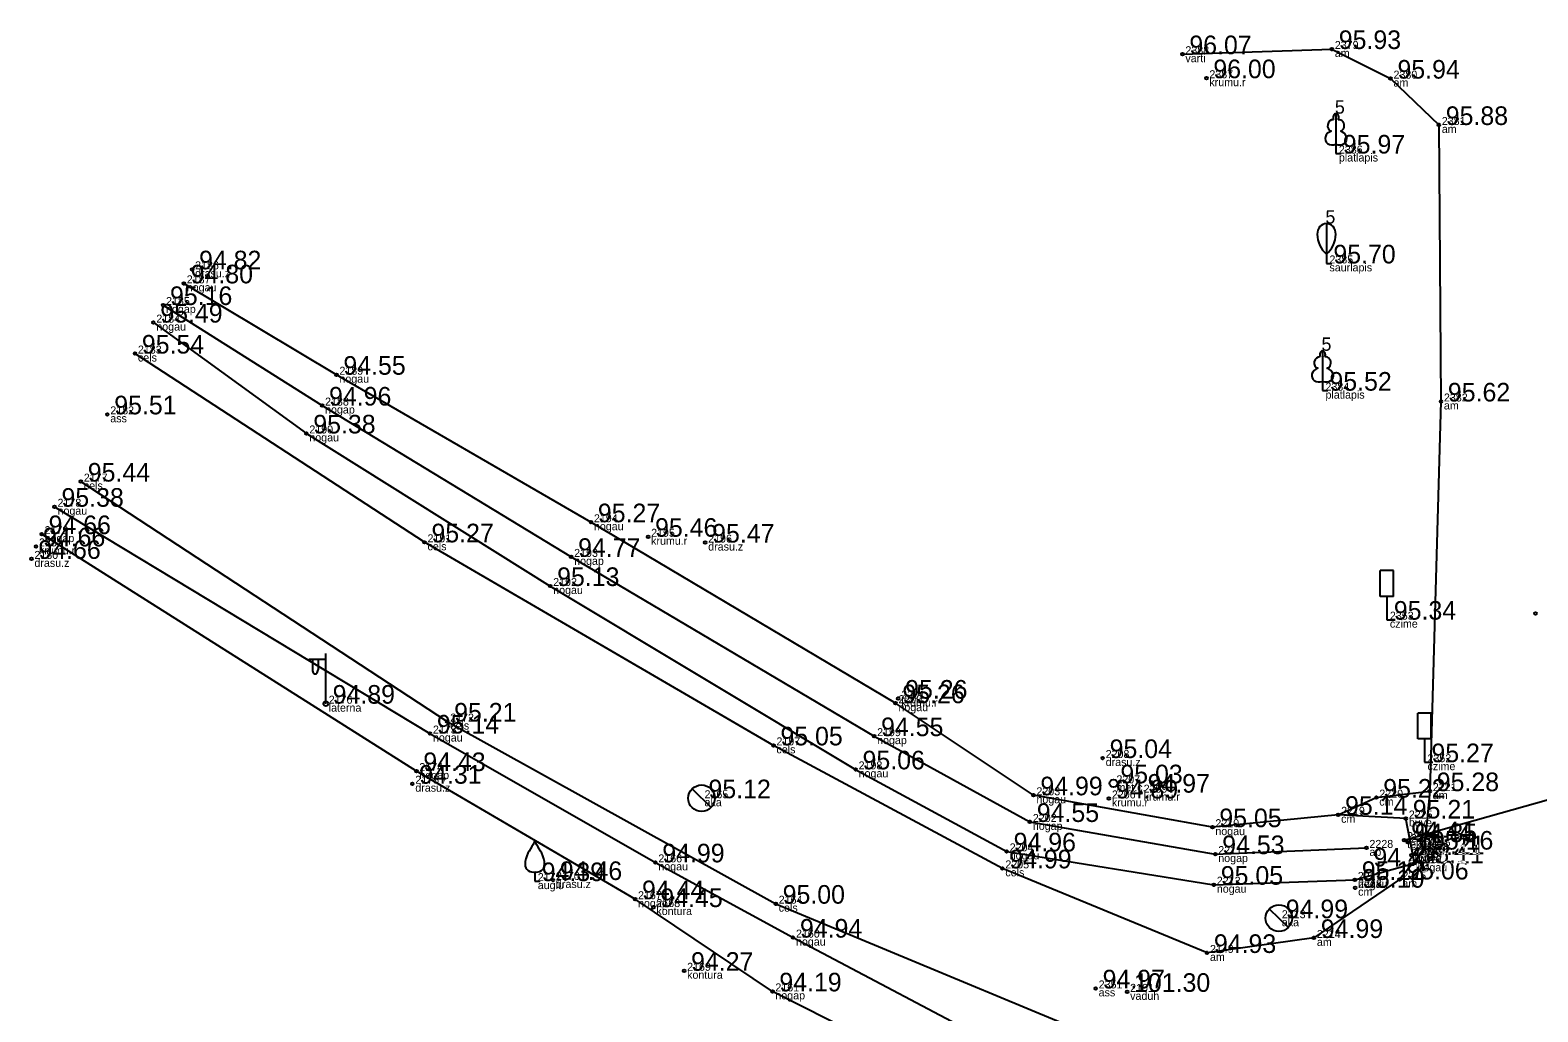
# Model space of a CAD drawing. Extents: x 614911 to 615803, y 262110 to 264311.
# Drawn here: x 615573.6 to 615630.3, y 263602.8 to 263639.7 of the extents above; entities that cross this region are included whole.
import ezdxf

# ---------------------------------------------------------------- set-up
doc = ezdxf.new("R2010")
doc.units = 0
for name, color, linetype in [('Level 1', 7, 'Continuous'), ('Level 11', 7, 'Continuous'), ('Level 12', 7, 'Continuous'), ('Level 14', 7, 'Continuous'), ('Level 16', 7, 'Continuous'), ('Level 31', 7, 'Continuous'), ('Level 37', 7, 'Continuous'), ('Level 44', 7, 'Continuous'), ('Level 53', 7, 'Continuous'), ('Level 54', 7, 'Continuous'), ('Level 57', 7, 'Continuous'), ('Level 58', 7, 'Continuous')]:
    doc.layers.add(name, color=color, linetype=linetype)

msp = doc.modelspace()

# ---------------------------------------------------------------- linework, layer by layer
at = {"layer": 'Level 1'}
for p, q in [((615622.678, 263635.413), (615622.678, 263635.066)), ((615622.678, 263635.066), (615622.878, 263635.066)), ((615622.322, 263631.284), (615622.322, 263630.932)), ((615622.322, 263630.932), (615622.522, 263630.932)), ((615622.174, 263626.492), (615622.174, 263626.145)), ((615622.174, 263626.145), (615622.374, 263626.145)), ((615592.559, 263608.045), (615592.559, 263607.693)), ((615592.559, 263607.693), (615592.759, 263607.693))]:
    msp.add_line(p, q, dxfattribs=at)
for points in [[(615622.678, 263636.566), (615622.678, 263635.413)], [(615622.768, 263636.334), (615622.767, 263636.335)], [(615622.322, 263632.432), (615622.322, 263631.284)], [(615622.174, 263627.645), (615622.174, 263626.492)], [(615622.264, 263627.413), (615622.263, 263627.414)]]:
    msp.add_lwpolyline(points, dxfattribs=at)
for centre, radius, start, end in [((615605.184, 263601.297), 14.88, 148.4844, 149.9901), ((615592.142, 263609.331), 0.439, 324.3837, 341.712), ((615592.976, 263609.331), 0.439, 198.288, 215.6163), ((615579.934, 263601.297), 14.88, 30.0099, 31.5156), ((615593.083, 263608.318), 0.89, 151.757, 179.9138), ((615592.483, 263608.324), 0.29, 181.0782, 285.2823), ((615592.635, 263608.324), 0.29, 254.7177, 358.9218), ((615592.035, 263608.318), 0.89, 0.0862, 28.243)]:
    msp.add_arc(centre, radius, start, end, dxfattribs=at)
for centre, major_axis, ratio, start_param, end_param in [((615622.55, 263636.121), (-0.039, -0.212), 0.861323, 3.141593, 6.283185), ((615622.678, 263636.416), (0, -0.15), 0.707107, 3.14537, 5.287485), ((615622.678, 263636.416), (0, -0.15), 0.707107, 0.995701, 3.137816), ((615622.806, 263636.121), (0.039, -0.212), 0.861323, 0, 3.141593), ((615622.588, 263635.659), (0.307, 0.095), 0.814445, 1.570796, 4.752015), ((615622.768, 263635.659), (-0.307, 0.095), 0.814445, 1.531171, 4.712389), ((615622.322, 263632.032), (0, 0.4), 0.875, 0, 1.570796), ((615622.322, 263632.032), (0, -0.4), 0.875, 1.570796, 3.141593), ((615622.797, 263632.055), (0, -0.943), 0.875, 4.7372, 5.669711), ((615621.847, 263632.055), (0, -0.943), 0.875, 0.613474, 1.545985), ((615622.174, 263627.495), (0, -0.15), 0.707107, 3.14537, 5.287485), ((615622.174, 263627.495), (0, -0.15), 0.707107, 0.995701, 3.137816), ((615622.046, 263627.2), (-0.039, -0.212), 0.861323, 3.141593, 6.283185), ((615622.302, 263627.2), (0.039, -0.212), 0.861323, 0, 3.141593), ((615622.084, 263626.738), (0.307, 0.095), 0.814445, 1.570796, 4.752015), ((615622.264, 263626.738), (-0.307, 0.095), 0.814445, 1.531171, 4.712389)]:
    msp.add_ellipse(centre, major_axis=major_axis, ratio=ratio, start_param=start_param, end_param=end_param, dxfattribs=at)
at = {"layer": 'Level 11'}
msp.add_line((615625.244, 263609.235), (615637.058, 263612.559), dxfattribs=at)
at = {"layer": 'Level 12'}
for p, q in [((615598.47, 263611.159), (615599.188, 263610.463)), ((615620.173, 263606.645), (615620.891, 263605.949))]:
    msp.add_line(p, q, dxfattribs=at)
for centre in [(615598.829, 263610.811), (615620.532, 263606.297)]:
    msp.add_circle(centre, 0.5, dxfattribs=at)
at = {"layer": 'Level 14'}
msp.add_circle((615614.315, 263611.373), 0.148, dxfattribs=at)
at = {"layer": 'Level 16'}
for p, q in [((615624.841, 263619.376), (615624.341, 263619.376)), ((615624.341, 263618.407), (615624.341, 263619.376)), ((615624.841, 263618.407), (615624.841, 263619.376)), ((615624.841, 263618.407), (615624.341, 263618.407)), ((615624.595, 263618.407), (615624.595, 263617.529)), ((615624.595, 263617.529), (615624.91, 263617.529)), ((615626.255, 263614.014), (615625.755, 263614.014)), ((615625.755, 263613.045), (615625.755, 263614.014)), ((615626.255, 263613.045), (615626.255, 263614.014)), ((615626.255, 263613.045), (615625.755, 263613.045)), ((615626.009, 263613.045), (615626.009, 263612.167)), ((615626.009, 263612.167), (615626.324, 263612.167))]:
    msp.add_line(p, q, dxfattribs=at)
at = {"layer": 'Level 31'}
for points in [[(615623.39, 263607.738), (615625.634, 263608.363), (615625.308, 263610.049), (615622.762, 263610.188), (615618.034, 263609.723), (615611.307, 263610.922), (615606.119, 263614.387), (615594.67, 263621.194), (615585.102, 263626.744), (615579.362, 263630.182)], [(615578.584, 263629.367), (615584.563, 263625.584), (615593.927, 263619.891), (615605.317, 263613.147), (615611.172, 263609.919), (615618.143, 263608.71), (615623.826, 263608.943)], [(615578.218, 263628.706), (615583.971, 263624.535), (615593.139, 263618.796), (615604.621, 263611.898), (615610.301, 263608.812), (615618.089, 263607.558), (615623.39, 263607.738)], [(615574.504, 263621.778), (615588.618, 263613.245), (615597.092, 263608.399), (615602.267, 263605.568), (615610.435, 263601.26), (615615.838, 263599.469), (615621.811, 263597.513), (615625.283, 263594.837), (615626.379, 263591.004)], [(615626.379, 263591.004), (615624.359, 263592.45), (615617.225, 263594.934), (615614.681, 263596.186), (615610.011, 263599.223), (615601.492, 263603.545), (615596.329, 263607.013), (615588.108, 263611.833), (615574.019, 263620.747)]]:
    msp.add_lwpolyline(points, dxfattribs=at)
at = {"layer": 'Level 37'}
for points in [[(615616.907, 263638.803), (615622.525, 263638.998), (615624.732, 263637.885), (615626.547, 263636.14), (615626.627, 263625.738), (615626.209, 263611.078), (615625.993, 263608.879), (615625.064, 263607.755), (615621.851, 263605.554), (615617.831, 263604.991), (615610.138, 263608.173), (615601.533, 263612.8), (615588.414, 263620.439), (615577.526, 263627.541)], [(615575.493, 263622.724), (615589.267, 263613.696), (615601.617, 263606.844), (615617.294, 263600.321), (615621.316, 263599.948), (615622.689, 263599.881), (615623.501, 263599.431), (615622.954, 263597.67), (615621.811, 263597.513), (615621.119, 263598.545), (615621.386, 263599.38), (615622.689, 263599.881)], [(615622.762, 263610.188), (615624.197, 263610.834), (615626.209, 263611.078)]]:
    msp.add_lwpolyline(points, dxfattribs=at)
at = {"layer": 'Level 44'}
for p, q in [((615584.699, 263614.369), (615584.699, 263616.252)), ((615584.699, 263616.032), (615584.064, 263616.032)), ((615584.199, 263616.032), (615584.199, 263615.64)), ((615584.409, 263616.032), (615584.409, 263615.64))]:
    msp.add_line(p, q, dxfattribs=at)
msp.add_circle((615584.699, 263614.369), 0.09, dxfattribs=at)
msp.add_ellipse((615584.304, 263615.64), major_axis=(0, 0.151), ratio=0.695971, start_param=1.570796, end_param=4.712389, dxfattribs=at)
at = {"layer": 'Level 57'}
for centre in [(615622.525, 263638.998), (615616.907, 263638.803), (615617.809, 263637.9), (615624.732, 263637.885), (615626.547, 263636.14), (615579.676, 263630.709), (615579.362, 263630.182), (615578.584, 263629.367), (615578.218, 263628.706), (615577.526, 263627.541), (615585.102, 263626.744), (615576.488, 263625.254), (615584.563, 263625.584), (615626.627, 263625.738), (615583.971, 263624.535), (615575.493, 263622.724), (615574.504, 263621.778), (615574.019, 263620.747), (615594.67, 263621.194), (615573.808, 263620.286), (615588.414, 263620.439), (615596.82, 263620.648), (615598.967, 263620.43), (615573.636, 263619.816), (615593.927, 263619.891), (615593.139, 263618.796), (615630.18, 263617.767), (615606.223, 263614.558), (615606.119, 263614.387), (615589.267, 263613.696), (615588.618, 263613.245), (615601.533, 263612.8), (615605.317, 263613.147), (615613.91, 263612.324), (615588.108, 263611.833), (615604.621, 263611.898), (615587.955, 263611.357), (615626.209, 263611.078), (615611.307, 263610.922), (615614.143, 263610.804), (615615.338, 263611.021), (615624.197, 263610.834), (615622.762, 263610.188), (615625.308, 263610.049), (615611.172, 263609.919), (615618.034, 263609.723), (615610.301, 263608.812), (615623.826, 263608.943), (615625.244, 263609.235), (615625.384, 263609.16), (615625.993, 263608.879), (615597.092, 263608.399), (615618.143, 263608.71), (615625.519, 263608.672), (615625.634, 263608.363), (615625.667, 263608.704), (615593.242, 263607.735), (615610.138, 263608.173), (615623.39, 263607.738), (615625.064, 263607.755), (615618.089, 263607.558), (615623.401, 263607.446), (615596.329, 263607.013), (615597.019, 263606.717), (615601.617, 263606.844), (615602.267, 263605.568), (615621.851, 263605.554), (615617.831, 263604.991), (615598.174, 263604.32), (615601.492, 263603.545), (615613.646, 263603.657), (615614.829, 263603.527)]:
    msp.add_circle(centre, 0.05, dxfattribs=at)
at = {"layer": 'Level 58'}
for centre in [(615622.525, 263638.998), (615616.907, 263638.803), (615617.809, 263637.9), (615624.732, 263637.885), (615626.547, 263636.14), (615579.676, 263630.709), (615579.362, 263630.182), (615578.584, 263629.367), (615578.218, 263628.706), (615577.526, 263627.541), (615585.102, 263626.744), (615576.488, 263625.254), (615584.563, 263625.584), (615626.627, 263625.738), (615583.971, 263624.535), (615575.493, 263622.724), (615574.504, 263621.778), (615574.019, 263620.747), (615594.67, 263621.194), (615573.808, 263620.286), (615588.414, 263620.439), (615596.82, 263620.648), (615598.967, 263620.43), (615573.636, 263619.816), (615593.927, 263619.891), (615593.139, 263618.796), (615630.18, 263617.767), (615606.223, 263614.558), (615606.119, 263614.387), (615589.267, 263613.696), (615588.618, 263613.245), (615601.533, 263612.8), (615605.317, 263613.147), (615613.91, 263612.324), (615588.108, 263611.833), (615604.621, 263611.898), (615587.955, 263611.357), (615626.209, 263611.078), (615611.307, 263610.922), (615614.143, 263610.804), (615615.338, 263611.021), (615624.197, 263610.834), (615622.762, 263610.188), (615625.308, 263610.049), (615611.172, 263609.919), (615618.034, 263609.723), (615610.301, 263608.812), (615623.826, 263608.943), (615625.244, 263609.235), (615625.384, 263609.16), (615625.993, 263608.879), (615597.092, 263608.399), (615618.143, 263608.71), (615625.519, 263608.672), (615625.634, 263608.363), (615625.667, 263608.704), (615593.242, 263607.735), (615610.138, 263608.173), (615623.39, 263607.738), (615625.064, 263607.755), (615618.089, 263607.558), (615623.401, 263607.446), (615596.329, 263607.013), (615597.019, 263606.717), (615601.617, 263606.844), (615602.267, 263605.568), (615621.851, 263605.554), (615617.831, 263604.991), (615598.174, 263604.32), (615601.492, 263603.545), (615613.646, 263603.657), (615614.829, 263603.527)]:
    msp.add_circle(centre, 0.05, dxfattribs=at)

# ---------------------------------------------------------------- texts
at = {"layer": 'Level 1'}
for p in [(615622.453, 263636.566), (615622.097, 263632.432), (615621.949, 263627.645)]:
    msp.add_text(' 5', height=0.5, dxfattribs=at).set_placement(p)
at = {"layer": 'Level 53'}
for s, p in [(' am', (615622.525, 263638.698)), (' varti', (615616.907, 263638.503)), (' krumu.r', (615617.809, 263637.6)), (' am', (615624.732, 263637.585)), (' am', (615626.547, 263635.84)), (' platlapis', (615622.678, 263634.766)), (' drasu.z', (615579.676, 263630.409)), (' saurlapis', (615622.322, 263630.632)), (' nogau', (615579.362, 263629.882)), (' nogap', (615578.584, 263629.067)), (' nogau', (615578.218, 263628.406)), (' cels', (615577.526, 263627.241)), (' nogau', (615585.102, 263626.444)), (' platlapis', (615622.174, 263625.845)), (' nogap', (615584.563, 263625.284)), (' am', (615626.627, 263625.438)), (' ass', (615576.488, 263624.954)), (' nogau', (615583.971, 263624.235)), (' cels', (615575.493, 263622.424)), (' nogau', (615574.504, 263621.478)), (' nogau', (615594.67, 263620.894)), (' krumu.r', (615573.808, 263619.986)), (' nogap', (615574.019, 263620.447)), (' cels', (615588.414, 263620.139)), (' krumu.r', (615596.82, 263620.348)), (' drasu.z', (615598.967, 263620.13)), (' drasu.z', (615573.636, 263619.516)), (' nogap', (615593.927, 263619.591)), (' nogau', (615593.139, 263618.496)), (' czime', (615624.595, 263617.229)), (' krumu.r', (615606.223, 263614.258)), (' laterna', (615584.699, 263614.069)), (' nogau', (615606.119, 263614.087)), (' cels', (615589.267, 263613.396)), (' nogau', (615588.618, 263612.945)), (' nogap', (615605.317, 263612.847)), (' cels', (615601.533, 263612.5)), (' drasu.z', (615613.91, 263612.024)), (' nogap', (615588.108, 263611.533)), (' nogau', (615604.621, 263611.598)), (' czime', (615626.009, 263611.867)), (' drasu.z', (615587.955, 263611.057)), (' met.c.', (615614.315, 263611.073)), (' aka', (615598.829, 263610.511)), (' nogau', (615611.307, 263610.622)), (' krumu.r', (615614.143, 263610.504)), (' krumu.r', (615615.338, 263610.721)), (' cm', (615624.197, 263610.534)), (' am', (615626.209, 263610.778)), (' cm', (615622.762, 263609.888)), (' buve', (615625.308, 263609.749)), (' nogap', (615611.172, 263609.619)), (' nogau', (615618.034, 263609.423)), (' ap', (615623.826, 263608.643)), (' tekne', (615625.244, 263608.935)), (' c.augsa', (615625.384, 263608.86)), (' nogau', (615597.092, 263608.099)), (' nogau', (615610.301, 263608.512)), (' nogap', (615618.143, 263608.41)), (' buve', (615625.519, 263608.372)), (' nogau', (615625.634, 263608.063)), (' buve', (615625.667, 263608.404)), (' am', (615625.993, 263608.579)), (' drasu.z', (615593.242, 263607.435)), (' cels', (615610.138, 263607.873)), (' auglu', (615592.559, 263607.393)), (' nogau', (615618.089, 263607.258)), (' nogau', (615623.39, 263607.438)), (' cm', (615623.401, 263607.146)), (' am', (615625.064, 263607.455)), (' nogap', (615596.329, 263606.713)), (' kontura', (615597.019, 263606.417)), (' cels', (615601.617, 263606.544)), (' aka', (615620.532, 263605.997)), (' nogau', (615602.267, 263605.268)), (' am', (615621.851, 263605.254)), (' am', (615617.831, 263604.691)), (' kontura', (615598.174, 263604.02)), (' nogap', (615601.492, 263603.245)), (' ass', (615613.646, 263603.357)), (' vaduh', (615614.829, 263603.227))]:
    msp.add_text(s, height=0.3, dxfattribs=at).set_placement(p)
at = {"layer": 'Level 54'}
for s, p in [(' 2388', (615616.907, 263638.803)), (' 2379', (615622.525, 263638.998)), (' 2387', (615617.809, 263637.9)), (' 2380', (615624.732, 263637.885)), (' 2381', (615626.547, 263636.14)), (' 2386', (615622.678, 263635.066)), (' 2186', (615579.676, 263630.709)), (' 2385', (615622.322, 263630.932)), (' 2187', (615579.362, 263630.182)), (' 2185', (615578.584, 263629.367)), (' 2184', (615578.218, 263628.706)), (' 2183', (615577.526, 263627.541)), (' 2189', (615585.102, 263626.744)), (' 2384', (615622.174, 263626.145)), (' 2188', (615584.563, 263625.584)), (' 2382', (615626.627, 263625.738)), (' 2182', (615576.488, 263625.254)), (' 2190', (615583.971, 263624.535)), (' 2177', (615575.493, 263622.724)), (' 2178', (615574.504, 263621.778)), (' 2194', (615594.67, 263621.194)), (' 2179', (615574.019, 263620.747)), (' 2195', (615596.82, 263620.648)), (' 2181', (615573.808, 263620.286)), (' 2191', (615588.414, 263620.439)), (' 2193', (615593.927, 263619.891)), (' 2196', (615598.967, 263620.43)), (' 2180', (615573.636, 263619.816)), (' 2192', (615593.139, 263618.796)), (' 2353', (615624.595, 263617.529)), (' 2176', (615584.699, 263614.369)), (' 2200', (615606.119, 263614.387)), (' 2201', (615606.223, 263614.558)), (' 2172', (615589.267, 263613.696)), (' 2173', (615588.618, 263613.245)), (' 2199', (615605.317, 263613.147)), (' 2197', (615601.533, 263612.8)), (' 2208', (615613.91, 263612.324)), (' 2352', (615626.009, 263612.167)), (' 2174', (615588.108, 263611.833)), (' 2198', (615604.621, 263611.898)), (' 2175', (615587.955, 263611.357)), (' 2203', (615611.307, 263610.922)), (' 2207', (615614.315, 263611.373)), (' 2209', (615615.338, 263611.021)), (' 2220', (615624.197, 263610.834)), (' 2221', (615626.209, 263611.078)), (' 2165', (615598.829, 263610.811)), (' 2206', (615614.143, 263610.804)), (' 2202', (615611.172, 263609.919)), (' 2210', (615618.034, 263609.723)), (' 2219', (615622.762, 263610.188)), (' 2225', (615625.308, 263610.049)), (' 2226', (615625.244, 263609.235)), (' 2227', (615625.384, 263609.16)), (' 2204', (615610.301, 263608.812)), (' 2211', (615618.143, 263608.71)), (' 2228', (615623.826, 263608.943)), (' 2224', (615625.519, 263608.672)), (' 2223', (615625.667, 263608.704)), (' 2222', (615625.993, 263608.879)), (' 2166', (615597.092, 263608.399)), (' 2205', (615610.138, 263608.173)), (' 2216', (615625.634, 263608.363)), (' 2171', (615592.559, 263607.693)), (' 2170', (615593.242, 263607.735)), (' 2212', (615618.089, 263607.558)), (' 2217', (615623.39, 263607.738)), (' 2218', (615623.401, 263607.446)), (' 2215', (615625.064, 263607.755)), (' 2167', (615596.329, 263607.013)), (' 2168', (615597.019, 263606.717)), (' 2164', (615601.617, 263606.844)), (' 2213', (615620.532, 263606.297)), (' 2160', (615602.267, 263605.568)), (' 2214', (615621.851, 263605.554)), (' 2149', (615617.831, 263604.991)), (' 2169', (615598.174, 263604.32)), (' 2161', (615601.492, 263603.545)), (' 2351', (615613.646, 263603.657)), (' 2101', (615614.829, 263603.527))]:
    msp.add_text(s, height=0.3, dxfattribs=at).set_placement(p)
at = {"layer": 'Level 58'}
for s, p in [(' 96.07', (615616.907, 263638.803)), (' 95.93', (615622.525, 263638.998)), (' 96.00', (615617.809, 263637.9)), (' 95.94', (615624.732, 263637.885)), (' 95.88', (615626.547, 263636.14)), (' 95.97', (615622.678, 263635.066)), (' 95.70', (615622.322, 263630.932)), (' 94.82', (615579.676, 263630.709)), (' 94.80', (615579.362, 263630.182)), (' 95.16', (615578.584, 263629.367)), (' 95.49', (615578.218, 263628.706)), (' 95.54', (615577.526, 263627.541)), (' 94.55', (615585.102, 263626.744)), (' 95.52', (615622.174, 263626.145)), (' 95.62', (615626.627, 263625.738)), (' 95.51', (615576.488, 263625.254)), (' 94.96', (615584.563, 263625.584)), (' 95.38', (615583.971, 263624.535)), (' 95.44', (615575.493, 263622.724)), (' 95.38', (615574.504, 263621.778)), (' 95.27', (615594.67, 263621.194)), (' 94.66', (615574.019, 263620.747)), (' 95.46', (615596.82, 263620.648)), (' 94.66', (615573.808, 263620.286)), (' 95.27', (615588.414, 263620.439)), (' 95.47', (615598.967, 263620.43)), (' 94.66', (615573.636, 263619.816)), (' 94.77', (615593.927, 263619.891)), (' 95.13', (615593.139, 263618.796)), (' 95.34', (615624.595, 263617.529)), (' 95.26', (615606.119, 263614.387)), (' 95.26', (615606.223, 263614.558)), (' 94.89', (615584.699, 263614.369)), (' 95.21', (615589.267, 263613.696)), (' 95.14', (615588.618, 263613.245)), (' 95.05', (615601.533, 263612.8)), (' 94.55', (615605.317, 263613.147)), (' 95.04', (615613.91, 263612.324)), (' 95.27', (615626.009, 263612.167)), (' 94.43', (615588.108, 263611.833)), (' 95.06', (615604.621, 263611.898)), (' 94.31', (615587.955, 263611.357)), (' 95.03', (615614.315, 263611.373)), (' 94.97', (615615.338, 263611.021)), (' 95.28', (615626.209, 263611.078)), (' 95.12', (615598.829, 263610.811)), (' 94.99', (615611.307, 263610.922)), (' 94.89', (615614.143, 263610.804)), (' 95.22', (615624.197, 263610.834)), (' 94.55', (615611.172, 263609.919)), (' 95.14', (615622.762, 263610.188)), (' 95.21', (615625.308, 263610.049)), (' 95.05', (615618.034, 263609.723)), (' 94.96', (615610.301, 263608.812)), (' 94.44', (615625.244, 263609.235)), (' 94.85', (615625.384, 263609.16)), (' 95.16', (615625.993, 263608.879)), (' 94.99', (615597.092, 263608.399)), (' 94.99', (615610.138, 263608.173)), (' 94.53', (615618.143, 263608.71)), (' 94.47', (615623.826, 263608.243)), (' 95.21', (615625.519, 263608.672)), (' 95.11', (615625.634, 263608.363)), (' 95.21', (615625.667, 263608.704)), (' 94.39', (615592.559, 263607.693)), (' 94.46', (615593.242, 263607.735)), (' 95.12', (615623.39, 263607.738)), (' 95.06', (615625.064, 263607.755)), (' 94.44', (615596.329, 263607.013)), (' 95.05', (615618.089, 263607.558)), (' 95.10', (615623.401, 263607.446)), (' 94.45', (615597.019, 263606.717)), (' 95.00', (615601.617, 263606.844)), (' 94.99', (615620.532, 263606.297)), (' 94.94', (615602.267, 263605.568)), (' 94.99', (615621.851, 263605.554)), (' 94.93', (615617.831, 263604.991)), (' 94.27', (615598.174, 263604.32)), (' 94.97', (615613.646, 263603.657)), (' 94.19', (615601.492, 263603.545)), (' 101.30', (615614.829, 263603.527))]:
    msp.add_text(s, height=0.7, dxfattribs=at).set_placement(p)

doc.saveas('drawing.dxf')
